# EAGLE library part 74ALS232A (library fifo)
FIFO
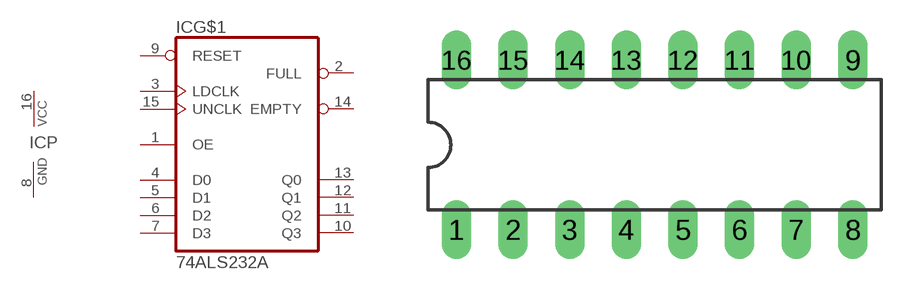
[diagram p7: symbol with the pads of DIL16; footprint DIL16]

Designator prefix IC; gates G$1=74232A P=PWRN

## 74ALS232A (OC_FARNELL: unknown; OC_NEWARK: unknown)  [DIL16]
1  G$1:OE  in
2  G$1:FULL  out
3  G$1:LDCLK  in
4  G$1:D0  in
5  G$1:D1  in
6  G$1:D2  in
7  G$1:D3  in
8  P:GND  pwr
9  G$1:RESET  in
10  G$1:Q3  hiz
11  G$1:Q2  hiz
12  G$1:Q1  hiz
13  G$1:Q0  hiz
14  G$1:EMPTY  out
15  G$1:UNCLK  in
16  P:VCC  pwr

## Footprint DIL16 (pad centres in mm)
Dual In Line Package
drill 0.813 long: 1 -8.89,-3.81; 2 -6.35,-3.81; 3 -3.81,-3.81; 4 -1.27,-3.81; 5 1.27,-3.81; 6 3.81,-3.81; 7 6.35,-3.81; 8 8.89,-3.81; 9 8.89,3.81; 10 6.35,3.81; 11 3.81,3.81; 12 1.27,3.81; 13 -1.27,3.81; 14 -3.81,3.81; 15 -6.35,3.81; 16 -8.89,3.81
